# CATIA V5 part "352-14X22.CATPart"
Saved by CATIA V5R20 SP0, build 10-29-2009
Part number: 352-14X22
Definition: NONE
Nomenclature: 352-14X22
Source: Unknown
Description: 352-14X22
Bounding box of the stored display mesh (mm): x 0 to 22, y -10 to 10, z -10 to 10
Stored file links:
  C:\Users\Utente\Desktop\IO LAVORO\3D X SITO CF\X SITO\PLASTICA\352\352-14X22.CATPart
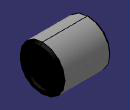
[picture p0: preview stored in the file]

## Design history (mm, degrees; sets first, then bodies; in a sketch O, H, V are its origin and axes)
Body1 "352-14X22" (main body)
  Solid1: solid without history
